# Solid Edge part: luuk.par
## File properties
Author: Blackblade
Template: Normal.par
Last saved by: Blackblade
Revision: 1
Application: Solid Edge
Accuracy: 0.990
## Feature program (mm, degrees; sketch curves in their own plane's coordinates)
sketch for "unnamed Protrusion 1" plane through (0, 0, 0) normal (0, 0, 1) x-axis (1, 0, 0)
  line (-20, -25) -> (20, -25)
  line (20, -25) -> (20, 25)
  line (20, 25) -> (-20, 25)
  line (-20, 25) -> (-20, -25)
extrude "unnamed Protrusion 1" add finite 1 along +normal
sketch for "ExtrudedProtrusion_2" plane through (0, 0, 1) normal (0, 0, 1) x-axis (0, 1, 0)
  line (26, 21) -> (-26, 21)
  line (-26, 21) -> (-26, -21)
  line (-26, -21) -> (26, -21)
  line (26, -21) -> (26, 21)
extrude "ExtrudedProtrusion_2" add finite 2 along +normal
fillet "Round_1" radius 2
cool vent "Vent_1"  RibThickness = 1 mm; RibDepth = 3 mm; SparThickness = 1 mm; SparDepth = 3 mm
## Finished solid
Body 1: solid body, 75 faces, 216 edges, 144 vertices.
  Faces by surface: plane 71, cylinder 4
  Edges by curve: line 212, ellipse 4
Bounding box of the edges (mm): 42.000 x 52.000 x 3.000, from (-21, -26, 0) to (21, 26, 3).
Cylindrical faces by radius (mm): R2 x4
Planar faces by outward normal: +x 17, +y 16, +z 1, -x 17, -y 18, -z 2
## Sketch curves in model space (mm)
line (10, 15.8356, 3) -> (-10, 15.8356, 3)
line (-10, 8.1808, 3) -> (10, 8.1808, 3)
line (-10, 11.9298, 3) -> (10, 11.9298, 3)
line (-5.2326, 19.4298, 3) -> (-5.2326, 4.4298, 3)
line (5.1731, 19.4298, 3) -> (5.1731, 4.4298, 3)
line (10, 4.4298, 3) -> (10, 19.4298, 3)
line (10, 19.4298, 3) -> (-10, 19.4298, 3)
line (-10, 19.4298, 3) -> (-10, 4.4298, 3)
line (-10, 4.4298, 3) -> (10, 4.4298, 3)
line (0, 19.4298, 3) -> (0, 4.5173, 3)
line (0, 19.4298, 3) -> (0, 4.5173, 3)
line (-21, -26, 1) -> (21, -26, 1)
line (21, -26, 1) -> (21, 26, 1)
line (21, 26, 1) -> (-21, 26, 1)
line (-21, 26, 1) -> (-21, -26, 1)
line (20, -25, 0) -> (20, 25, 0)
line (20, 25, 0) -> (-20, 25, 0)
line (-20, 25, 0) -> (-20, -25, 0)
line (-20, -25, 0) -> (20, -25, 0)
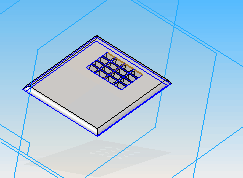
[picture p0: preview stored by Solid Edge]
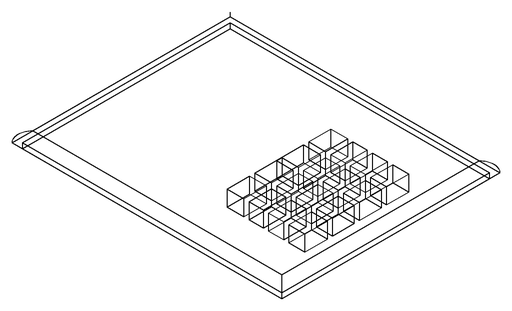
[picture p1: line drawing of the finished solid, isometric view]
